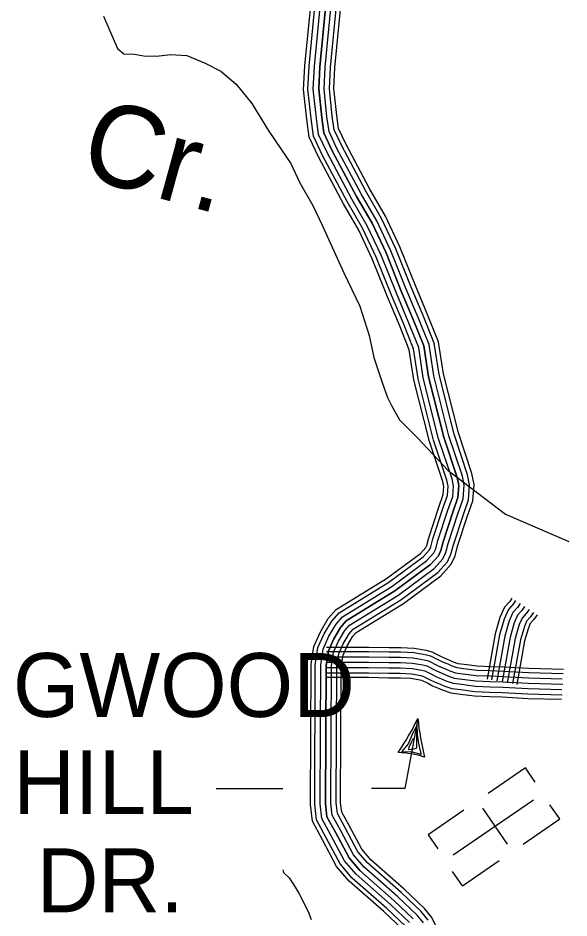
# Model space of a CAD drawing. Extents: x 1788175 to 1969470, y 584502 to 738744.
# Drawn here: x 1842071 to 1845259, y 658752 to 663962 of the extents above; entities that cross this region are included whole.
import ezdxf

# ---------------------------------------------------------------- set-up
doc = ezdxf.new("R2010")
doc.units = 0
for name, color, linetype in [('DESIGN - DRAINAGE - Bridges and Cross Drains Size Text', 7, 'Continuous'), ('DESIGN - ROW - Right-of-Way and Easement Labels', 7, 'Continuous'), ('DESIGN - TRANSPORTATION - Text', 7, 'Continuous'), ('DESIGN - UTILITIES - Cable (Underground) with Text', 7, 'Continuous'), ('SURVEY - CONTOURS - Index with Text', 7, 'Continuous'), ('SURVEY - TRANSPORTATION - Roads', 7, 'Continuous')]:
    doc.layers.add(name, color=color, linetype=linetype)

msp = doc.modelspace()

# ---------------------------------------------------------------- linework, layer by layer
at = {"layer": 'DESIGN - ROW - Right-of-Way and Easement Labels'}
for p, q in [((1844356.8, 659824.7), (1844376.9, 659859.8)), ((1844376.9, 659859.8), (1844376.3, 659734.1)), ((1844378.1, 659872.5), (1844380.7, 659814)), ((1844330.2, 659759.4), (1844356.8, 659824.7)), ((1844380.7, 659814), (1844387.7, 659762.2)), ((1844291, 659713.7), (1844330.2, 659759.4)), ((1844333.4, 659740.6), (1844348.3, 659770.2)), ((1844348.3, 659770.2), (1844358.7, 659793.2)), ((1844387.7, 659762.2), (1844397.2, 659718.6)), ((1844354.1, 659712.2), (1844291, 659713.7)), ((1844332.8, 659725.6), (1844333.4, 659740.6)), ((1844360.3, 659728.3), (1844332.8, 659725.6)), ((1844404.5, 659699), (1844354.1, 659712.2)), ((1844376.3, 659734.1), (1844360.3, 659728.3)), ((1844397.2, 659718.6), (1844404.5, 659699))]:
    msp.add_line(p, q, dxfattribs=at)
for points in [[(1844384.3, 659907.1), (1844310.1, 659500.4), (1844116.5, 659500.4)], [(1843603.3, 659500.2), (1843218.4, 659500.1)]]:
    msp.add_lwpolyline(points, dxfattribs=at)
for centre, radius, start, end in [((1843130.7, 660499.2), 1386.4, 325.2793, 334.7178), ((1845928.6, 660063.6), 1552.3, 185.7876, 194.2154), ((1844255.6, 659177.5), 532.3, 71.5708, 88.4292)]:
    msp.add_arc(centre, radius, start, end, dxfattribs=at)
at = {"layer": 'DESIGN - TRANSPORTATION - Text'}
for points in [[(1842565.4, 663972.8), (1842647, 663785.7), (1842682.6, 663755.2), (1842744.5, 663752.5), (1842808.7, 663741.7), (1842860.2, 663743.1), (1842872, 663741.8)], [(1842872, 663741.8), (1842952.6, 663750.4), (1843048.4, 663745.3), (1843153.7, 663700), (1843245.1, 663654.8), (1843334, 663579.7), (1843424.5, 663466.5), (1843518.5, 663313.2), (1843595, 663198.2), (1843650, 663119.4), (1843702.5, 663008.7), (1843776.8, 662875.7), (1843831.3, 662762.9), (1843955.7, 662487.2), (1844049.2, 662293.8), (1844103, 662123), (1844129.4, 661996.6), (1844177.6, 661851.9), (1844208.5, 661765.4), (1844231.9, 661719.1), (1844278.2, 661636.6), (1844383.2, 661531.7), (1844560.8, 661342.8), (1844891.3, 661090.5), (1845258.9, 660931.9)], [(1843603.6, 659031.1), (1843608, 659015.2), (1843639.7, 658983.4), (1843665.1, 658945.4), (1843696.8, 658894.6), (1843728.5, 658831.2), (1843753.9, 658780.4), (1843766.6, 658742.4)]]:
    msp.add_lwpolyline(points, dxfattribs=at)
at = {"layer": 'DESIGN - UTILITIES - Cable (Underground) with Text'}
for p, q in [((1845006.6, 659620.9), (1844791.7, 659473.1)), ((1845063.1, 659538.8), (1845007, 659620.4)), ((1844904.1, 659178.7), (1844760.4, 659387.6)), ((1845205.3, 659325.1), (1845148.8, 659407.3)), ((1844650.9, 659376.2), (1844443.7, 659233.6)), ((1844993.8, 659179.7), (1845205.3, 659325.2)), ((1844443.8, 659233.6), (1844499.5, 659152.6)), ((1844642.4, 658937.9), (1844855, 659084.2)), ((1844642.4, 658938.1), (1844585.9, 659020))]:
    msp.add_line(p, q, dxfattribs=at)
msp.add_lwpolyline([(1845053.6, 659433.7), (1844589.8, 659114.5)], dxfattribs=at)
at = {"layer": 'SURVEY - CONTOURS - Index with Text'}
for points in [[(1844294.8, 658687.9), (1844187.8, 658789), (1843987.5, 658965.5), (1843914.6, 659050.5), (1843832.7, 659204), (1843774.5, 659311.5), (1843763.3, 659409.5), (1843766.6, 660220), (1843782.8, 660323.8), (1843820.7, 660408.6), (1843866.4, 660485), (1843912.7, 660538.3), (1844203.5, 660716.8), (1844399.3, 660861.7), (1844430.3, 660897.2), (1844435.9, 660908.8), (1844447.2, 660952.9), (1844505.2, 661129.7), (1844531.1, 661203.3), (1844534.5, 661250), (1844528.7, 661279.3), (1844451.3, 661510.8), (1844361.4, 661867.9), (1844335.2, 662040.7), (1844277.9, 662183.7), (1844208.7, 662347.2), (1844121.1, 662567.2), (1844042.7, 662733.2), (1843954.4, 662887), (1843811.3, 663154.8), (1843756.5, 663271.7), (1843742, 663376.4), (1843723.9, 663548.9), (1843730.4, 663685.7), (1843774.1, 664132.7)], [(1844313, 658704.7), (1844204.5, 658807.3), (1844005.1, 658982.9), (1843935.1, 659064.5), (1843854.5, 659215.7), (1843798.5, 659319.1), (1843788, 659410.9), (1843791.3, 660218), (1843806.7, 660316.7), (1843842.7, 660397.1), (1843886.5, 660470.4), (1843928.9, 660519.3), (1844217.3, 660696.3), (1844416.1, 660843.4), (1844451.1, 660883.5), (1844459.2, 660900.2), (1844471, 660945.9), (1844528.6, 661121.7), (1844555.5, 661198.2), (1844559.4, 661251.5), (1844552.6, 661285.6), (1844475, 661517.7), (1844385.6, 661872.7), (1844359.3, 662047.2), (1844300.8, 662193.2), (1844231.5, 662356.6), (1844143.8, 662577.1), (1844064.6, 662744.6), (1843976, 662899), (1843833.4, 663165.9), (1843780.4, 663278.8), (1843766.5, 663379.4), (1843748.7, 663549.6), (1843755.1, 663683.9), (1843798.7, 664129.9)], [(1844335.7, 658725.9), (1844225.4, 658830.2), (1844027.2, 659004.7), (1843960.9, 659082.1), (1843881.8, 659230.4), (1843828.6, 659328.6), (1843819, 659412.6), (1843822.3, 660215.5), (1843836.7, 660307.8), (1843870.3, 660382.8), (1843911.7, 660452.2), (1843949.2, 660495.3), (1844234.7, 660670.6), (1844437.3, 660820.5), (1844477.1, 660866.2), (1844488.4, 660889.4), (1844500.7, 660937.2), (1844558, 661111.8), (1844586.1, 661191.8), (1844590.6, 661253.4), (1844582.6, 661293.6), (1844504.8, 661526.4), (1844416.1, 661878.8), (1844389.4, 662055.4), (1844329.4, 662205), (1844260.2, 662368.3), (1844172.2, 662589.5), (1844092.1, 662759), (1844003.1, 662914), (1843861.1, 663179.8), (1843810.5, 663287.7), (1843797.3, 663383.1), (1843779.7, 663550.4), (1843786, 663681.6), (1843829.5, 664126.5)], [(1843860.3, 664123.1), (1843816.9, 663679.4), (1843810.8, 663551.3), (1843828.1, 663386.9), (1843840.6, 663296.6), (1843888.8, 663193.7), (1844030.3, 662929), (1844119.6, 662773.4), (1844200.7, 662601.8), (1844288.9, 662380.1), (1844358.1, 662216.8), (1844419.5, 662063.6), (1844446.5, 661885), (1844534.6, 661535.1), (1844612.6, 661301.6), (1844621.9, 661255.4), (1844616.7, 661185.4), (1844587.3, 661101.8), (1844530.5, 660928.5), (1844517.7, 660878.7), (1844503.2, 660848.9), (1844458.4, 660797.6), (1844252.1, 660644.9), (1843969.5, 660471.4), (1843936.9, 660433.9), (1843897.8, 660368.5), (1843866.7, 660298.9), (1843853.3, 660213.1), (1843850, 659414.3), (1843858.7, 659338), (1843909.1, 659245.1), (1843986.6, 659099.7), (1844049.4, 659026.5), (1844246.3, 658853.1), (1844358.4, 658747.1)], [(1844358.4, 658747.1), (1844246.3, 658853.1), (1844049.4, 659026.5), (1843986.6, 659099.7), (1843909.1, 659245.1), (1843858.7, 659338), (1843850, 659414.3), (1843853.3, 660213.1), (1843866.7, 660298.9), (1843897.8, 660368.5), (1843936.9, 660433.9), (1843969.5, 660471.4), (1844252.1, 660644.9), (1844458.4, 660797.6), (1844503.2, 660848.9), (1844517.7, 660878.7), (1844530.5, 660928.5), (1844587.3, 661101.8), (1844616.7, 661185.4), (1844621.9, 661255.4), (1844612.6, 661301.6), (1844534.6, 661535.1), (1844446.5, 661885), (1844419.5, 662063.6), (1844358.1, 662216.8), (1844288.9, 662380.1), (1844200.7, 662601.8), (1844119.6, 662773.4), (1844030.3, 662929), (1843888.8, 663193.7), (1843840.6, 663296.6), (1843828.1, 663386.9), (1843810.8, 663551.3), (1843816.9, 663679.4), (1843860.3, 664123.1)], [(1844418, 658723.3), (1844381.1, 658768.3), (1844267.2, 658876), (1844071.5, 659048.4), (1844012.4, 659117.3), (1843936.4, 659259.8), (1843888.8, 659347.5), (1843881, 659416), (1843884.3, 660210.6), (1843896.7, 660290.1), (1843925.4, 660354.2), (1843962.1, 660415.7), (1843989.7, 660447.5), (1844269.4, 660619.2), (1844479.5, 660774.7), (1844529.3, 660831.6), (1844546.9, 660868), (1844560.3, 660919.8), (1844616.7, 661091.8), (1844647.3, 661179), (1844653.1, 661257.3), (1844642.6, 661309.5), (1844564.4, 661543.8), (1844476.9, 661891.1), (1844449.6, 662071.8), (1844386.8, 662228.6), (1844317.6, 662391.9), (1844229.1, 662614.2), (1844147.1, 662787.7), (1844057.4, 662944), (1843916.5, 663207.5), (1843870.6, 663305.5), (1843858.8, 663390.6), (1843841.9, 663552.2), (1843847.9, 663677.1), (1843891.1, 664119.7)], [(1844444.4, 658740), (1844403.9, 658789.5), (1844288.1, 658898.9), (1844093.6, 659070.2), (1844038.1, 659134.9), (1843963.7, 659274.5), (1843919, 659357), (1843912, 659417.7), (1843915.3, 660208.1), (1843926.7, 660281.2), (1843952.9, 660339.8), (1843987.3, 660397.4), (1844010, 660423.6), (1844286.8, 660593.5), (1844500.7, 660751.8), (1844555.4, 660814.4), (1844576.2, 660857.2), (1844590, 660911.1), (1844646, 661081.8), (1844677.9, 661172.6), (1844684.3, 661259.2), (1844672.7, 661317.5), (1844594.1, 661552.5), (1844507.4, 661897.2), (1844479.7, 662080), (1844415.4, 662240.4), (1844346.2, 662403.7), (1844257.5, 662626.6), (1844174.6, 662802.1), (1844084.5, 662959.1), (1843944.3, 663221.4), (1843900.7, 663314.4), (1843889.6, 663394.3), (1843873, 663553.1), (1843878.8, 663674.9), (1843921.9, 664116.3)], [(1844558.5, 658561), (1844466.2, 658753.9), (1844422.7, 658807), (1844305.4, 658917.9), (1844111.9, 659088.3), (1844059.5, 659149.4), (1843986.4, 659286.6), (1843943.9, 659364.9), (1843937.7, 659419.1), (1843941, 660206.1), (1843951.5, 660273.8), (1843975.8, 660328), (1844008.2, 660382.3), (1844026.8, 660403.7), (1844301.2, 660572.1), (1844518.2, 660732.7), (1844577, 660800), (1844600.4, 660848.3), (1844614.7, 660903.9), (1844670.4, 661073.6), (1844703.3, 661167.3), (1844710.2, 661260.8), (1844697.6, 661324.1), (1844618.8, 661559.8), (1844532.6, 661902.3), (1844504.7, 662086.8), (1844439.2, 662250.2), (1844370, 662413.5), (1844281.1, 662636.8), (1844197.4, 662814), (1844107, 662971.5), (1843967.2, 663233), (1843925.6, 663321.8), (1843915.2, 663397.5), (1843898.8, 663553.8), (1843904.5, 663673), (1843947.5, 664113.5)]]:
    msp.add_lwpolyline(points, dxfattribs=at)
at = {"layer": 'SURVEY - TRANSPORTATION - Roads'}
for points in [[(1844928.8, 660604), (1844916.1, 660584.9), (1844886.5, 660552), (1844859.5, 660490.5), (1844832.3, 660396.6), (1844785.4, 660134.6)], [(1844950.2, 660589.8), (1844936.4, 660569.1), (1844908.4, 660537.9), (1844883.8, 660481.7), (1844857.3, 660390.7), (1844810.7, 660130.1)], [(1844976, 660572.6), (1844961, 660550.1), (1844934.7, 660520.9), (1844913, 660471.1), (1844887.6, 660383.6), (1844841.2, 660124.6)], [(1845001.8, 660555.4), (1844985.5, 660531), (1844961.1, 660503.9), (1844942.2, 660460.5), (1844917.8, 660376.6), (1844871.7, 660119.2)], [(1845001.8, 660555.4), (1844985.5, 660531), (1844961.1, 660503.9), (1844942.2, 660460.5), (1844917.8, 660376.6), (1844871.7, 660119.2)], [(1845027.6, 660538.2), (1845010.1, 660511.9), (1844987.5, 660486.9), (1844971.4, 660450), (1844948, 660369.5), (1844902.2, 660113.7)], [(1845053.4, 660521), (1845034.6, 660492.9), (1845013.9, 660469.9), (1845000.6, 660439.4), (1844978.2, 660362.4), (1844932.8, 660108.3)], [(1845073.9, 660507.3), (1845054.2, 660477.6), (1845035, 660456.3), (1845023.9, 660431), (1845002.3, 660356.8), (1844957.1, 660103.9)], [(1843856.3, 660319.4), (1843961.5, 660319.5), (1844100.7, 660319.5), (1844217.2, 660316.8), (1844285.6, 660316.8), (1844363.8, 660313.8), (1844432.2, 660301.3), (1844465.9, 660292.9), (1844523.2, 660264.3), (1844541.6, 660255), (1844566.9, 660244.9), (1844589.8, 660234.8), (1844615.4, 660225.6), (1844652.5, 660221.3), (1844727.5, 660210.9), (1844804.4, 660208.4), (1844881.2, 660205.6), (1845027, 660197.5), (1845226.4, 660192.7)], [(1843856.3, 660294.7), (1843961.5, 660294.8), (1844100.4, 660294.8), (1844216.9, 660292.1), (1844285.1, 660292.1), (1844361.1, 660289.1), (1844427, 660277.2), (1844457.3, 660269.6), (1844512.1, 660242.2), (1844531.5, 660232.5), (1844557.3, 660222.2), (1844580.6, 660211.8), (1844609.7, 660201.4), (1844649.4, 660196.7), (1844725.4, 660186.3), (1844803.5, 660183.7), (1844880.1, 660180.9), (1845026, 660172.8), (1845226.1, 660168)], [(1843856.3, 660263.7), (1843961.5, 660263.8), (1844100, 660263.8), (1844216.5, 660261.1), (1844284.5, 660261.1), (1844357.7, 660258.2), (1844420.5, 660246.8), (1844446.5, 660240.3), (1844498.3, 660214.4), (1844518.8, 660204.2), (1844545.2, 660193.6), (1844569.1, 660183), (1844602.6, 660171), (1844645.5, 660166), (1844722.7, 660155.3), (1844802.4, 660152.7), (1844878.7, 660149.9), (1845024.8, 660141.8), (1845219.1, 660137.1)], [(1843856.3, 660232.7), (1843961.5, 660232.8), (1844099.7, 660232.8), (1844216.2, 660230.1), (1844283.9, 660230.1), (1844354.4, 660227.3), (1844414, 660216.5), (1844435.6, 660211.1), (1844484.4, 660186.7), (1844506.1, 660175.9), (1844533.2, 660165), (1844557.6, 660154.2), (1844595.5, 660140.7), (1844641.5, 660135.2), (1844720.1, 660124.4), (1844801.4, 660121.7), (1844877.2, 660119), (1845023.5, 660110.8), (1845059.6, 660110)], [(1843856.3, 660232.7), (1843961.5, 660232.8), (1844099.7, 660232.8), (1844216.2, 660230.1), (1844283.9, 660230.1), (1844354.4, 660227.3), (1844414, 660216.5), (1844435.6, 660211.1), (1844484.4, 660186.7), (1844506.1, 660175.9), (1844533.2, 660165), (1844557.6, 660154.2), (1844595.5, 660140.7), (1844641.5, 660135.2), (1844720.1, 660124.4), (1844801.4, 660121.7), (1844877.2, 660119), (1845023.5, 660110.8), (1845222.8, 660106)], [(1843856.4, 660201.7), (1843961.5, 660201.8), (1844099.3, 660201.8), (1844215.8, 660199.1), (1844283.3, 660199.1), (1844351, 660196.5), (1844407.4, 660186.2), (1844424.8, 660181.8), (1844470.5, 660159), (1844493.4, 660147.6), (1844521.1, 660136.5), (1844546, 660125.4), (1844588.4, 660110.3), (1844637.6, 660104.5), (1844717.5, 660093.5), (1844800.3, 660090.7), (1844875.8, 660088), (1845022.3, 660079.9), (1845217.3, 660075.1)], [(1843856.4, 660170.7), (1843961.5, 660170.8), (1844099, 660170.8), (1844215.5, 660168.1), (1844282.7, 660168.1), (1844347.6, 660165.6), (1844400.9, 660155.9), (1844414, 660152.6), (1844456.7, 660131.3), (1844480.7, 660119.3), (1844509.1, 660107.9), (1844534.5, 660096.6), (1844581.3, 660079.9), (1844633.7, 660073.7), (1844714.8, 660062.5), (1844799.2, 660059.7), (1844874.4, 660057), (1845021.1, 660048.9), (1845219, 660044.1)], [(1843856.4, 660145), (1843961.6, 660145), (1844098.7, 660145), (1844215.2, 660142.3), (1844282.2, 660142.3), (1844344.8, 660139.9), (1844395.5, 660130.7), (1844405, 660128.3), (1844445.2, 660108.3), (1844470.1, 660095.8), (1844499.1, 660084.2), (1844524.9, 660072.7), (1844575.4, 660054.7), (1844630.4, 660048.2), (1844712.6, 660036.9), (1844798.4, 660034), (1844873.2, 660031.3), (1845020, 660023.2), (1845215.4, 660018.4)]]:
    msp.add_lwpolyline(points, dxfattribs=at)

# ---------------------------------------------------------------- texts
at = {"layer": 'DESIGN - DRAINAGE - Bridges and Cross Drains Size Text'}
msp.add_text('Cr.', height=475, rotation=344.6691, dxfattribs=at).set_placement((1842411.4, 663049.3))
at = {"layer": 'DESIGN - ROW - Right-of-Way and Easement Labels'}
for s, p in [('DOGWOOD', (1841299.5, 659915.6)), ('HILL', (1842043.3, 659353)), ('DR.', (1842179.3, 658784.8))]:
    msp.add_text(s, height=370, dxfattribs=at).set_placement(p)

doc.saveas('drawing.dxf')
